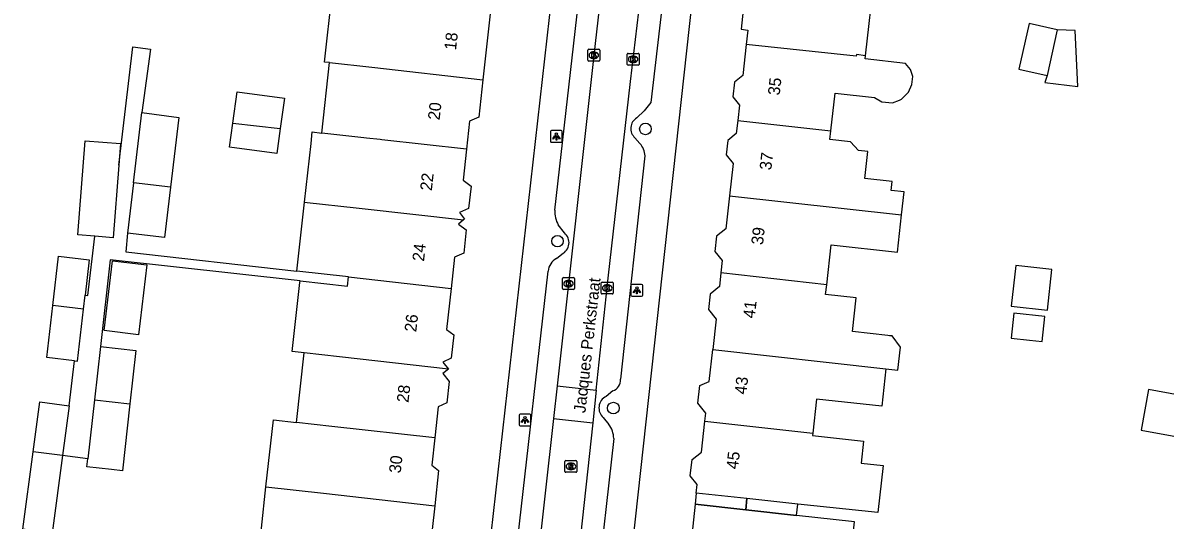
# Model space of a CAD drawing. Extents: x 161258 to 161838, y 380836 to 381727.
# Drawn here: x 161664.6 to 161760.9, y 381384.3 to 381426.2 of the extents above; entities that cross this region are included whole.
import ezdxf

# ---------------------------------------------------------------- set-up
doc = ezdxf.new("R2010")
doc.units = 0
for name, color, linetype in [('IMGEO_Boom', 7, 'Continuous'), ('IMGEO_Kolk', 7, 'Continuous'), ('IMGEO_Lichtpunt', 7, 'Continuous'), ('IMGEO_Openbare_ruimte_label', 7, 'Continuous'), ('IMGEO_Pand', 7, 'Continuous'), ('IMGEO_Pand_nummerreeks', 7, 'Continuous'), ('IMGEO_Pand_overbouw', 7, 'Continuous'), ('IMGEO_Rijbaan_lokaal_open', 7, 'Continuous'), ('IMGEO_Rioolput', 7, 'Continuous'), ('IMGEO_Voetpad_open', 7, 'Continuous')]:
    doc.layers.add(name, color=color, linetype=linetype)

msp = doc.modelspace()

# ---------------------------------------------------------------- linework, layer by layer
at = {"layer": 'IMGEO_Boom'}
for centre in [(161717.079, 381417.26), (161709.672, 381407.8), (161714.376, 381393.732)]:
    msp.add_circle(centre, 0.489, dxfattribs=at)
at = {"layer": 'IMGEO_Kolk'}
for p, q in [((161712.229, 381423.052), (161712.229, 381423.904)), ((161712.304, 381423.978), (161713.156, 381423.978)), ((161713.23, 381423.904), (161713.23, 381423.052)), ((161713.156, 381422.978), (161712.304, 381422.978)), ((161712.74, 381423.198), (161712.715, 381423.198)), ((161712.717, 381423.758), (161712.742, 381423.758)), ((161715.542, 381422.708), (161715.542, 381423.56)), ((161715.617, 381423.634), (161716.469, 381423.634)), ((161716.053, 381422.854), (161716.028, 381422.854)), ((161716.03, 381423.414), (161716.055, 381423.414)), ((161716.543, 381423.56), (161716.543, 381422.708)), ((161716.469, 381422.634), (161715.617, 381422.634)), ((161710.094, 381403.802), (161710.094, 381404.654)), ((161710.169, 381404.728), (161711.021, 381404.728)), ((161711.095, 381404.654), (161711.095, 381403.802)), ((161711.021, 381403.728), (161710.169, 381403.728)), ((161710.605, 381403.948), (161710.58, 381403.948)), ((161710.582, 381404.508), (161710.607, 381404.508)), ((161713.362, 381403.425), (161713.362, 381404.277)), ((161713.437, 381404.351), (161714.289, 381404.351)), ((161713.85, 381404.131), (161713.875, 381404.131)), ((161714.363, 381404.277), (161714.363, 381403.425)), ((161714.289, 381403.351), (161713.437, 381403.351)), ((161713.873, 381403.571), (161713.848, 381403.571))]:
    msp.add_line(p, q, dxfattribs=at)
for points in [[(161712.229, 381423.052), (161712.229, 381423.904)], [(161712.304, 381423.978), (161713.156, 381423.978)], [(161713.23, 381423.904), (161713.23, 381423.052)], [(161713.156, 381422.978), (161712.304, 381422.978)], [(161712.55, 381423.678), (161712.673, 381423.678), (161712.673, 381423.527), (161712.803, 381423.678), (161712.967, 381423.678), (161712.821, 381423.527), (161712.974, 381423.278), (161712.822, 381423.278), (161712.737, 381423.442), (161712.673, 381423.375), (161712.673, 381423.278), (161712.55, 381423.278), (161712.55, 381423.678)], [(161715.542, 381422.708), (161715.542, 381423.56)], [(161715.617, 381423.634), (161716.469, 381423.634)], [(161715.863, 381423.334), (161715.986, 381423.334), (161715.986, 381423.183), (161716.116, 381423.334), (161716.28, 381423.334), (161716.134, 381423.183), (161716.287, 381422.934), (161716.135, 381422.934), (161716.05, 381423.098), (161715.986, 381423.031), (161715.986, 381422.934), (161715.863, 381422.934), (161715.863, 381423.334)], [(161716.543, 381423.56), (161716.543, 381422.708)], [(161716.469, 381422.634), (161715.617, 381422.634)], [(161710.094, 381403.802), (161710.094, 381404.654)], [(161710.169, 381404.728), (161711.021, 381404.728)], [(161711.095, 381404.654), (161711.095, 381403.802)], [(161711.021, 381403.728), (161710.169, 381403.728)], [(161710.415, 381404.428), (161710.538, 381404.428), (161710.538, 381404.277), (161710.668, 381404.428), (161710.832, 381404.428), (161710.686, 381404.277), (161710.839, 381404.028), (161710.687, 381404.028), (161710.602, 381404.192), (161710.538, 381404.125), (161710.538, 381404.028), (161710.415, 381404.028), (161710.415, 381404.428)], [(161713.362, 381403.425), (161713.362, 381404.277)], [(161713.437, 381404.351), (161714.289, 381404.351)], [(161713.683, 381404.051), (161713.806, 381404.051), (161713.806, 381403.9), (161713.936, 381404.051), (161714.1, 381404.051), (161713.954, 381403.9), (161714.107, 381403.651), (161713.955, 381403.651), (161713.87, 381403.815), (161713.806, 381403.748), (161713.806, 381403.651), (161713.683, 381403.651), (161713.683, 381404.051)], [(161714.363, 381404.277), (161714.363, 381403.425)], [(161714.289, 381403.351), (161713.437, 381403.351)]]:
    msp.add_lwpolyline(points, dxfattribs=at)
for centre, start, end in [((161712.306, 381423.902), 91.55205, 178.44795), ((161712.306, 381423.902), 91.55205, 178.44795), ((161713.154, 381423.902), 1.55205, 88.44795), ((161713.154, 381423.902), 1.55205, 88.44795), ((161712.306, 381423.054), 181.55205, 268.44795), ((161712.306, 381423.054), 181.55205, 268.44795), ((161713.154, 381423.054), 271.55205, 358.44795), ((161713.154, 381423.054), 271.55205, 358.44795), ((161715.619, 381423.558), 91.55205, 178.44795), ((161715.619, 381423.558), 91.55205, 178.44795), ((161716.467, 381423.558), 1.55205, 88.44795), ((161716.467, 381423.558), 1.55205, 88.44795), ((161715.619, 381422.71), 181.55205, 268.44795), ((161715.619, 381422.71), 181.55205, 268.44795), ((161716.467, 381422.71), 271.55205, 358.44795), ((161716.467, 381422.71), 271.55205, 358.44795), ((161710.171, 381404.652), 91.55205, 178.44795), ((161710.171, 381404.652), 91.55205, 178.44795), ((161711.019, 381404.652), 1.55205, 88.44795), ((161711.019, 381404.652), 1.55205, 88.44795), ((161710.171, 381403.804), 181.55205, 268.44795), ((161710.171, 381403.804), 181.55205, 268.44795), ((161711.019, 381403.804), 271.55205, 358.44795), ((161711.019, 381403.804), 271.55205, 358.44795), ((161713.439, 381404.275), 91.55205, 178.44795), ((161713.439, 381404.275), 91.55205, 178.44795), ((161714.287, 381404.275), 1.55205, 88.44795), ((161714.287, 381404.275), 1.55205, 88.44795), ((161713.439, 381403.427), 181.55205, 268.44795), ((161713.439, 381403.427), 181.55205, 268.44795), ((161714.287, 381403.427), 271.55205, 358.44795), ((161714.287, 381403.427), 271.55205, 358.44795)]:
    msp.add_arc(centre, 0.0765, start, end, dxfattribs=at)
for centre, major_axis, ratio, start_param, end_param in [((161712.716, 381423.478), (-0.387, 0.002), 0.722429, 4.712389, 7.853982), ((161712.741, 381423.478), (-0.39, 0.002), 0.717154, 1.570796, 4.712389), ((161716.029, 381423.134), (-0.387, 0.002), 0.722429, 4.712389, 7.853982), ((161716.054, 381423.134), (-0.39, 0.002), 0.717154, 1.570796, 4.712389), ((161710.581, 381404.228), (-0.387, 0.002), 0.722429, 4.712389, 7.853982), ((161710.606, 381404.228), (-0.39, 0.002), 0.717154, 1.570796, 4.712389), ((161713.849, 381403.851), (-0.387, 0.002), 0.722429, 4.712389, 7.853982), ((161713.874, 381403.851), (-0.39, 0.002), 0.717154, 1.570796, 4.712389)]:
    msp.add_ellipse(centre, major_axis=major_axis, ratio=ratio, start_param=start_param, end_param=end_param, dxfattribs=at)
at = {"layer": 'IMGEO_Lichtpunt'}
for p, q in [((161709.98, 381417.13), (161709.172, 381417.13)), ((161709.98, 381417.13), (161709.172, 381417.13)), ((161709.078, 381417.035), (161709.078, 381416.228)), ((161709.078, 381417.035), (161709.078, 381416.228)), ((161709.172, 381416.134), (161709.98, 381416.134)), ((161709.172, 381416.134), (161709.98, 381416.134)), ((161710.074, 381416.228), (161710.074, 381417.035)), ((161710.074, 381416.228), (161710.074, 381417.035)), ((161715.858, 381404.067), (161715.858, 381403.26)), ((161715.858, 381404.067), (161715.858, 381403.26)), ((161716.76, 381404.162), (161715.952, 381404.162)), ((161716.76, 381404.162), (161715.952, 381404.162)), ((161716.854, 381403.26), (161716.854, 381404.067)), ((161716.854, 381403.26), (161716.854, 381404.067)), ((161715.952, 381403.166), (161716.76, 381403.166)), ((161715.952, 381403.166), (161716.76, 381403.166)), ((161706.431, 381393.13), (161706.431, 381392.323)), ((161706.431, 381393.13), (161706.431, 381392.323)), ((161707.333, 381393.225), (161706.525, 381393.225)), ((161707.333, 381393.225), (161706.525, 381393.225)), ((161707.427, 381392.323), (161707.427, 381393.13)), ((161707.427, 381392.323), (161707.427, 381393.13)), ((161706.525, 381392.229), (161707.333, 381392.229)), ((161706.525, 381392.229), (161707.333, 381392.229))]:
    msp.add_line(p, q, dxfattribs=at)
for points in [[(161709.452, 381416.699), (161709.491, 381416.671), (161709.303, 381416.409), (161709.265, 381416.436), (161709.452, 381416.699)], [(161709.554, 381416.651), (161709.601, 381416.651), (161709.601, 381416.329), (161709.554, 381416.329), (161709.554, 381416.651)], [(161709.664, 381416.671), (161709.702, 381416.698), (161709.889, 381416.436), (161709.85, 381416.408), (161709.664, 381416.671)], [(161716.232, 381403.731), (161716.271, 381403.703), (161716.083, 381403.441), (161716.045, 381403.468), (161716.232, 381403.731)], [(161716.334, 381403.683), (161716.381, 381403.683), (161716.381, 381403.361), (161716.334, 381403.361), (161716.334, 381403.683)], [(161716.444, 381403.703), (161716.482, 381403.73), (161716.669, 381403.468), (161716.63, 381403.44), (161716.444, 381403.703)], [(161706.805, 381392.794), (161706.844, 381392.766), (161706.656, 381392.504), (161706.618, 381392.531), (161706.805, 381392.794)], [(161706.907, 381392.746), (161706.954, 381392.746), (161706.954, 381392.424), (161706.907, 381392.424), (161706.907, 381392.746)], [(161707.017, 381392.766), (161707.055, 381392.793), (161707.242, 381392.531), (161707.203, 381392.503), (161707.017, 381392.766)]]:
    msp.add_lwpolyline(points, dxfattribs=at)
for centre in [(161709.577, 381416.833), (161716.357, 381403.865), (161706.93, 381392.928)]:
    msp.add_circle(centre, 0.0994, dxfattribs=at)
for centre, start, end in [((161709.172, 381417.035), 90, 180), ((161709.172, 381417.035), 90, 180), ((161709.98, 381417.035), 0, 90), ((161709.98, 381417.035), 0, 90), ((161709.172, 381416.228), 180, 270), ((161709.172, 381416.228), 180, 270), ((161709.98, 381416.228), 270, 0), ((161709.98, 381416.228), 270, 360), ((161715.952, 381404.067), 90, 180), ((161715.952, 381404.067), 90, 180), ((161716.76, 381404.067), 0, 90), ((161716.76, 381404.067), 0, 90), ((161715.952, 381403.26), 180, 270), ((161715.952, 381403.26), 180, 270), ((161716.76, 381403.26), 270, 0), ((161716.76, 381403.26), 270, 360), ((161706.525, 381393.13), 90, 180), ((161706.525, 381393.13), 90, 180), ((161707.333, 381393.13), 0, 90), ((161707.333, 381393.13), 0, 90), ((161706.525, 381392.323), 180, 270), ((161706.525, 381392.323), 180, 270), ((161707.333, 381392.323), 270, 0), ((161707.333, 381392.323), 270, 360)]:
    msp.add_arc(centre, 0.0946, start, end, dxfattribs=at)
at = {"layer": 'IMGEO_Pand'}
for points in [[(161726.363, 381431.292), (161726.065, 381428.576), (161725.464, 381428.642), (161725.137, 381425.659), (161725.695, 381425.598), (161725.563, 381424.391)], [(161735.633, 381423.432), (161736.369, 381430.138)], [(161690.466, 381422.857), (161690.037, 381422.905), (161690.682, 381428.718)], [(161704.027, 381427.222), (161703.383, 381421.411)], [(161751.784, 381425.616), (161749.411, 381426.146), (161748.552, 381422.295), (161750.925, 381421.766)], [(161750.925, 381421.766), (161750.747, 381421.184), (161753.518, 381420.833), (161753.284, 381425.55), (161751.784, 381425.616)], [(161751.784, 381425.616), (161750.925, 381421.766)], [(161725.563, 381424.391), (161725.274, 381421.762), (161724.572, 381421.198), (161724.437, 381419.965), (161724.997, 381419.267), (161724.855, 381417.975)], [(161735.633, 381423.432), (161734.857, 381423.524), (161734.841, 381423.385), (161725.563, 381424.391)], [(161689.807, 381416.916), (161690.466, 381422.857)], [(161690.466, 381422.857), (161694.013, 381422.464), (161703.383, 381421.411)], [(161732.709, 381417.1), (161733.059, 381420.284), (161736.384, 381419.919), (161737.01, 381419.535), (161737.909, 381419.467), (161738.476, 381419.689), (161738.67, 381419.765), (161739.247, 381420.37), (161739.525, 381421.003), (161739.623, 381421.67), (161739.424, 381422.273), (161739.002, 381422.791), (161735.604, 381423.164), (161735.633, 381423.432)], [(161703.383, 381421.411), (161703.033, 381418.258), (161702.263, 381417.921), (161701.999, 381415.545)], [(161682.315, 381417.758), (161682.673, 381420.404), (161686.658, 381419.865), (161686.313, 381417.308)], [(161673.95, 381412.711), (161674.654, 381418.636)], [(161674.654, 381418.636), (161677.751, 381418.218), (161677.053, 381412.342)], [(161686.313, 381417.308), (161686.027, 381415.19), (161682.041, 381415.728), (161682.315, 381417.758)], [(161682.315, 381417.758), (161686.313, 381417.308)], [(161724.855, 381417.975), (161724.734, 381416.871), (161724.019, 381416.297), (161723.885, 381415.071), (161724.46, 381414.354), (161724.161, 381411.63)], [(161724.855, 381417.975), (161732.709, 381417.1)], [(161738.668, 381410.013), (161738.88, 381411.952), (161737.797, 381412.071), (161737.882, 381412.843), (161735.567, 381413.097), (161735.815, 381415.35), (161735.033, 381415.436), (161734.361, 381416.184), (161732.629, 381416.374), (161732.709, 381417.1)], [(161670.674, 381408.213), (161669.255, 381408.322), (161669.867, 381416.273), (161672.845, 381416.044), (161672.703, 381414.201)], [(161688.353, 381411.095), (161688.902, 381416.042), (161689.009, 381417.005), (161689.807, 381416.916)], [(161701.999, 381415.545), (161694.873, 381416.346), (161694.723, 381416.363), (161693.585, 381416.491), (161693.353, 381416.517), (161689.807, 381416.916)], [(161701.999, 381415.545), (161701.711, 381412.946), (161702.382, 381412.452), (161702.171, 381410.548), (161701.4, 381410.21), (161701.842, 381409.658), (161701.758, 381409.591)], [(161672.703, 381414.201), (161672.233, 381408.093), (161670.674, 381408.213)], [(161673.95, 381412.711), (161673.447, 381408.48)], [(161677.053, 381412.342), (161676.55, 381408.111), (161673.447, 381408.48)], [(161677.053, 381412.342), (161673.95, 381412.711)], [(161724.161, 381411.63), (161723.856, 381408.847), (161723.08, 381408.225), (161722.937, 381406.928), (161723.554, 381406.159), (161723.44, 381405.121)], [(161724.161, 381411.63), (161738.668, 381410.013)], [(161687.708, 381405.274), (161688.353, 381411.095)], [(161688.353, 381411.095), (161688.568, 381411.071), (161692.697, 381410.608), (161693.204, 381410.551), (161701.758, 381409.591)], [(161701.758, 381409.591), (161701.323, 381409.243), (161701.982, 381408.758), (161701.765, 381406.796), (161700.999, 381406.461), (161700.706, 381403.814)], [(161732.352, 381404.128), (161732.721, 381407.493), (161738.324, 381406.878), (161738.668, 381410.013)], [(161667.145, 381402.381), (161667.633, 381406.532), (161670.215, 381406.229), (161669.864, 381403.236)], [(161672.166, 381406.153), (161675.076, 381405.807), (161674.376, 381399.915), (161671.466, 381400.261), (161672.166, 381406.153)], [(161747.903, 381402.324), (161750.947, 381401.984), (161751.329, 381405.412), (161748.285, 381405.752), (161747.903, 381402.324)], [(161692.051, 381404.786), (161687.708, 381405.274)], [(161687.979, 381404.466), (161691.966, 381404.018), (161692.051, 381404.786)], [(161692.051, 381404.786), (161700.706, 381403.814)], [(161723.44, 381405.121), (161723.314, 381403.969), (161722.532, 381403.342), (161722.389, 381402.039), (161723.033, 381401.236), (161722.751, 381398.66)], [(161732.352, 381404.128), (161723.44, 381405.121)], [(161688.336, 381398.388), (161687.318, 381398.503), (161687.709, 381402.034), (161687.962, 381404.311), (161687.979, 381404.466)], [(161700.706, 381403.814), (161700.322, 381400.353), (161700.942, 381399.897), (161700.724, 381397.929), (161700.003, 381397.614), (161700.474, 381397.025)], [(161737.346, 381397.034), (161738.085, 381396.952), (161738.352, 381396.922), (161738.567, 381398.88), (161737.857, 381399.809), (161737.653, 381399.831), (161737.512, 381399.846), (161734.516, 381400.175), (161734.83, 381403.038), (161732.263, 381403.319), (161732.352, 381404.128)], [(161669.727, 381402.067), (161669.864, 381403.236)], [(161668.958, 381397.715), (161666.63, 381397.987), (161667.145, 381402.381)], [(161669.727, 381402.067), (161667.145, 381402.381)], [(161668.958, 381397.715), (161669.212, 381397.685), (161669.727, 381402.067)], [(161749.454, 381399.452), (161750.5, 381399.336), (161750.735, 381401.439), (161748.129, 381401.73), (161747.894, 381399.626), (161749.454, 381399.452)], [(161671.159, 381398.929), (161670.655, 381394.43)], [(161671.159, 381398.929), (161674.152, 381398.594), (161673.647, 381394.095)], [(161687.686, 381392.516), (161688.336, 381398.388)], [(161700.474, 381397.025), (161691.304, 381398.055), (161688.336, 381398.388)], [(161722.083, 381392.634), (161722.158, 381393.316), (161721.498, 381394.138), (161721.662, 381395.631), (161722.457, 381395.98), (161722.751, 381398.66)], [(161722.751, 381398.66), (161737.346, 381397.034)], [(161700.474, 381397.025), (161700.01, 381396.654), (161700.552, 381395.976), (161700.351, 381394.166), (161699.62, 381393.846), (161699.328, 381391.212)], [(161737.346, 381397.034), (161737.001, 381393.886), (161731.499, 381394.49), (161731.184, 381391.62)], [(161765.076, 381390.715), (161765.709, 381394.135), (161759.471, 381395.29), (161758.838, 381391.869), (161764.068, 381390.901)], [(161665.487, 381390.035), (161666.051, 381394.262), (161668.515, 381393.933)], [(161673.647, 381394.095), (161673.015, 381388.455), (161672.09, 381388.558), (161670.023, 381388.792), (161670.097, 381389.449)], [(161670.655, 381394.43), (161670.097, 381389.449)], [(161670.655, 381394.43), (161673.647, 381394.095)], [(161668.515, 381393.933), (161667.955, 381389.734)], [(161685.107, 381387.097), (161685.733, 381392.733), (161687.686, 381392.516)], [(161699.328, 381391.212), (161690.653, 381392.186), (161687.686, 381392.516)], [(161731.184, 381391.62), (161731.163, 381391.425), (161735.466, 381390.952), (161735.261, 381389.087), (161737.099, 381388.885), (161736.666, 381384.941), (161729.912, 381385.632), (161725.633, 381386.102), (161721.364, 381386.571), (161721.439, 381387.297), (161720.857, 381388.023), (161721.007, 381389.393), (161721.797, 381390.026), (161722.083, 381392.634)], [(161722.083, 381392.634), (161731.184, 381391.62)], [(161699.328, 381391.212), (161699.072, 381388.907), (161699.655, 381388.478), (161699.325, 381385.5)], [(161667.955, 381389.734), (161667.084, 381383.196), (161664.619, 381383.525), (161665.487, 381390.035)], [(161667.955, 381389.734), (161665.487, 381390.035)], [(161699.325, 381385.5), (161698.686, 381379.746), (161693.717, 381380.297), (161689.477, 381380.767), (161689.323, 381379.378), (161684.313, 381379.934), (161684.467, 381381.323), (161684.72, 381383.604), (161685.107, 381387.097)], [(161685.107, 381387.097), (161689.961, 381386.552), (161699.325, 381385.5)], [(161734.025, 381378.077), (161734.377, 381381.323), (161734.687, 381384.152), (161729.808, 381384.687), (161725.536, 381385.156), (161721.267, 381385.625), (161720.995, 381382.98), (161720.225, 381382.362), (161720.079, 381381.03), (161720.691, 381380.268), (161720.625, 381379.67)]]:
    msp.add_lwpolyline(points, dxfattribs=at)
at = {"layer": 'IMGEO_Pand_overbouw'}
for points in [[(161725.633, 381386.102), (161721.364, 381386.571), (161721.267, 381385.625), (161725.536, 381385.156)], [(161729.912, 381385.632), (161725.633, 381386.102), (161725.536, 381385.156), (161729.808, 381384.687)]]:
    msp.add_lwpolyline(points, close=True, dxfattribs=at)
at = {"layer": 'IMGEO_Rijbaan_lokaal_open'}
for points in [[(161714.193, 381436.286), (161712.841, 381424.462), (161709.639, 381395.601)], [(161712.933, 381395.246), (161713.952, 381404.688), (161715.817, 381421.255), (161717.229, 381433.087), (161717.434, 381435.638)], [(161709.639, 381395.601), (161709.333, 381392.858)], [(161709.639, 381395.601), (161712.933, 381395.246)], [(161712.933, 381395.246), (161712.637, 381392.502)], [(161709.333, 381392.858), (161707.873, 381379.766)], [(161709.333, 381392.858), (161712.637, 381392.502)], [(161712.637, 381392.502), (161710.748, 381374.936)]]:
    msp.add_lwpolyline(points, dxfattribs=at)
at = {"layer": 'IMGEO_Rioolput'}
for p, q in [((161710.301, 381388.39), (161710.301, 381389.242)), ((161710.376, 381389.316), (161711.228, 381389.316)), ((161711.302, 381389.242), (161711.302, 381388.39)), ((161711.228, 381388.316), (161710.376, 381388.316)), ((161710.812, 381388.536), (161710.787, 381388.536)), ((161710.789, 381389.096), (161710.814, 381389.096))]:
    msp.add_line(p, q, dxfattribs=at)
for points in [[(161710.301, 381388.39), (161710.301, 381389.242)], [(161710.376, 381389.316), (161711.228, 381389.316)], [(161711.302, 381389.242), (161711.302, 381388.39)], [(161711.228, 381388.316), (161710.376, 381388.316)], [(161710.89, 381389.014), (161710.638, 381389.016), (161710.638, 381388.616)], [(161710.638, 381388.616), (161710.762, 381388.616), (161710.762, 381388.778), (161710.773, 381388.778)], [(161710.816, 381388.935), (161710.762, 381388.935), (161710.762, 381388.854)], [(161710.762, 381388.854), (161710.814, 381388.854)], [(161710.82, 381388.749), (161710.891, 381388.616), (161711.031, 381388.616), (161710.966, 381388.742)]]:
    msp.add_lwpolyline(points, dxfattribs=at)
for centre, radius, start, end in [((161710.378, 381389.24), 0.0765, 91.55205, 178.44795), ((161710.378, 381389.24), 0.0765, 91.55205, 178.44795), ((161711.226, 381389.24), 0.0765, 1.55205, 88.44795), ((161711.226, 381389.24), 0.0765, 1.55205, 88.44795), ((161710.378, 381388.392), 0.0765, 181.55205, 268.44795), ((161710.378, 381388.392), 0.0765, 181.55205, 268.44795), ((161710.772, 381388.725), 0.0533, 26.02933, 88.69889), ((161710.798, 381389.043), 0.19, 274.7715, 282.96867), ((161710.822, 381388.839), 0.0964, 77.00612, 93.18647), ((161710.836, 381388.896), 0.0378, 276.66336, 79.67722), ((161710.889, 381388.904), 0.109, 350.36119, 89.41601), ((161710.887, 381388.904), 0.112, 277.58423, 350.98172), ((161710.871, 381388.689), 0.108, 29.51342, 73.79051), ((161711.226, 381388.392), 0.0765, 271.55205, 358.44795), ((161711.226, 381388.392), 0.0765, 271.55205, 358.44795)]:
    msp.add_arc(centre, radius, start, end, dxfattribs=at)
for centre, major_axis, ratio, start_param, end_param in [((161710.788, 381388.816), (-0.387, 0.002), 0.722429, 4.712389, 7.853982), ((161710.813, 381388.816), (-0.39, 0.002), 0.717154, 1.570796, 4.712389)]:
    msp.add_ellipse(centre, major_axis=major_axis, ratio=ratio, start_param=start_param, end_param=end_param, dxfattribs=at)
at = {"layer": 'IMGEO_Voetpad_open'}
for points in [[(161703.682, 381379.623), (161710.363, 381438.89), (161702.199, 381460.88)], [(161715.1, 381373.857), (161721.934, 381436.431)], [(161709.448, 381410.412), (161711.97, 381432.657)], [(161719.053, 381432.543), (161717.543, 381419.485), (161716.981, 381418.776), (161716.345, 381418.195)], [(161672.703, 381414.201), (161673.874, 381424.194), (161675.377, 381423.991), (161674.654, 381418.636)], [(161716.198, 381416.519), (161716.616, 381416.048)], [(161717.043, 381414.993), (161714.978, 381396.161)], [(161673.447, 381408.48), (161673.296, 381406.895), (161687.708, 381405.274)], [(161710.253, 381408.492), (161709.735, 381409.167)], [(161669.864, 381403.236), (161670.087, 381403.21), (161670.674, 381408.213)], [(161709.584, 381406.349), (161710.03, 381406.715)], [(161687.979, 381404.466), (161671.979, 381406.238), (161671.159, 381398.929)], [(161706.333, 381382.735), (161708.87, 381405.285)], [(161668.515, 381393.933), (161668.958, 381397.715)], [(161714.339, 381395.173), (161713.766, 381394.706)], [(161713.531, 381392.929), (161713.986, 381392.356)], [(161714.413, 381391.161), (161712.928, 381377.964)], [(161670.097, 381389.449), (161667.955, 381389.734)]]:
    msp.add_lwpolyline(points, dxfattribs=at)
for centre, radius, start, end in [((161716.886, 381417.303), 1.043, 121.25948, 228.71548), ((161715.3, 381414.901), 1.746, 3.01067, 41.05957), ((161711.736, 381410.284), 2.292, 176.79439, 209.16796), ((161709.582, 381407.674), 1.058, 295.04573, 50.64869), ((161710.252, 381405.129), 1.39, 118.69508, 173.57754), ((161713.989, 381396.1), 0.991, 290.69923, 3.51433), ((161714.232, 381393.74), 1.072, 115.75633, 229.17689), ((161712.398, 381391.115), 2.015, 1.31303, 38.01284)]:
    msp.add_arc(centre, radius, start, end, dxfattribs=at)

# ---------------------------------------------------------------- texts
at = {"layer": 'IMGEO_Openbare_ruimte_label'}
msp.add_text('Jacques Perkstraat', height=1, rotation=83.57125, dxfattribs=at).set_placement((161712.016, 381393.281))
at = {"layer": 'IMGEO_Pand_nummerreeks'}
for s, rotation, p in [('18', 83.67476, (161701.118, 381423.866)), ('35', 83.65757, (161728.382, 381420.056)), ('20', 83.70913, (161699.736, 381417.973)), ('37', 83.65757, (161727.681, 381413.752)), ('22', 83.70913, (161699.079, 381412.013)), ('39', 83.65934, (161726.981, 381407.449)), ('24', 83.70913, (161698.422, 381406.063)), ('41', 83.65757, (161726.292, 381401.258)), ('26', 83.70913, (161697.766, 381400.109)), ('43', 83.65934, (161725.58, 381394.843)), ('28', 83.70913, (161697.11, 381394.158)), ('30', 83.70913, (161696.454, 381388.204)), ('45', 83.65757, (161724.879, 381388.539))]:
    msp.add_text(s, height=1, rotation=rotation, dxfattribs=at).set_placement(p)

doc.saveas('drawing.dxf')
